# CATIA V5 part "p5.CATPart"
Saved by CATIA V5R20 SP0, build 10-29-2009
Part number: p5
Publications: "Line.1", "Plane.2", "Plane.3"
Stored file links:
  D:\Dropbox\IAO_2011\MMS_GR2\IAO_2011_1439_jlicbarski\p5.CATPart
  D:\Dropbox\IAO_2011\MMS_GR2\IAO_2011_1439_jlicbarski\train.CATProduct

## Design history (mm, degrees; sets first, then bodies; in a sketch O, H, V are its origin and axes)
AxisSystem1: origin (0, 0, 0), X (1, 0, 0), Y (0, 1, 0), Z (0, 0, 1)
Set1
  Point1: linked copy from another document
  Point2: linked copy from another document
Body1 (main body)
  Line1: type PtDir, RefPoint Point1, Direction edge [XY plane of AxisSystem1 | ZX plane of AxisSystem1], Start 0, End -40
  Plane1: type Normal, Curve Line1
  Plane2: type 3Points, Element1 Point1, Element2 vertex of Line1, Element3 Point2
